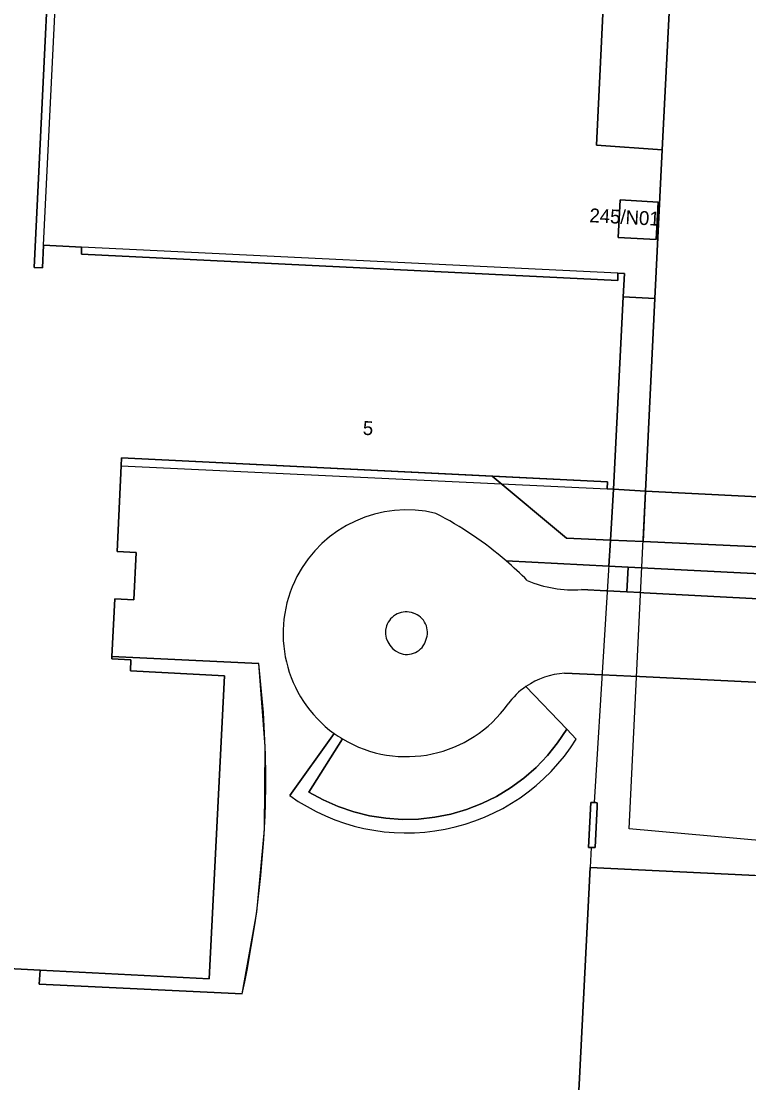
# Model space of a CAD drawing. Extents: x 161758 to 162722, y 384793 to 385405.
# Drawn here: x 162011.7 to 162064.1, y 385249.7 to 385326.1 of the extents above; entities that cross this region are included whole.
import ezdxf

# ---------------------------------------------------------------- set-up
doc = ezdxf.new("R2010")
doc.units = 0
for name, color, linetype in [('IMGEO_Erf', 7, 'Continuous'), ('IMGEO_Groenvoorziening', 7, 'Continuous'), ('IMGEO_Haag', 7, 'Continuous'), ('IMGEO_Muur', 7, 'Continuous'), ('IMGEO_Pand', 7, 'Continuous'), ('IMGEO_Pand_nummerreeks', 7, 'Continuous'), ('IMGEO_Pand_overbouw', 7, 'Continuous'), ('IMGEO_Parkeervlak_open', 7, 'Continuous'), ('IMGEO_Rijbaan_lokaal_gesloten', 7, 'Continuous'), ('IMGEO_Rijbaan_lokaal_open', 7, 'Continuous'), ('IMGEO_Voetpad_open', 7, 'Continuous')]:
    doc.layers.add(name, color=color, linetype=linetype)

msp = doc.modelspace()

# ---------------------------------------------------------------- linework, layer by layer
at = {"layer": 'IMGEO_Erf'}
for points in [[(162000.222, 385344.237), (162014.352, 385343.552), (162012.641, 385308.403), (162013.228, 385308.374), (162013.321, 385310.001), (162015.604, 385309.889), (162016.05, 385309.863), (162016.038, 385309.353), (162054.674, 385307.455), (162054.682, 385307.985), (162055.146, 385307.978), (162055.062, 385306.286), (162057.335, 385306.161), (162057.875, 385316.893), (162053.132, 385317.221), (162054.39, 385343.133)], [(162046.639, 385287.263), (162054.026, 385286.89), (162054.142, 385288.756), (162050.979, 385288.899), (162045.633, 385293.362), (162018.94, 385294.688), (162018.914, 385294.105), (162018.606, 385287.935), (162019.994, 385287.867), (162019.826, 385284.453), (162018.438, 385284.521), (162018.242, 385280.372), (162028.809, 385279.859)], [(162121.521, 385275.665), (162083.133, 385277.615), (162056.237, 385278.926), (162055.602, 385278.957), (162053.548, 385279.049), (162050.835, 385279.171)], [(162048.062, 385278.214), (162050.992, 385275.146), (162051.687, 385274.418)], [(162034.242, 385274.83), (162031.044, 385270.355)], [(162031.044, 385270.355), (162034.242, 385274.83)], [(162051.687, 385274.418), (162050.992, 385275.146), (162050.338, 385274.163), (162049.601, 385273.242), (162048.787, 385272.388), (162047.9, 385271.609), (162046.949, 385270.911), (162045.941, 385270.298), (162044.883, 385269.776), (162043.783, 385269.348), (162042.65, 385269.018), (162041.492, 385268.789), (162040.319, 385268.661), (162039.14, 385268.637), (162037.962, 385268.716), (162036.796, 385268.897), (162035.651, 385269.18), (162034.534, 385269.561), (162033.455, 385270.039), (162032.422, 385270.61), (162034.844, 385274.435)], [(162051.88, 385249.095), (162051.925, 385250), (162052.677, 385265.163), (162064.107, 385264.629)], [(162027.622, 385256.076), (162012.996, 385256.776), (162013.072, 385257.772), (162010.781, 385257.887), (162008.908, 385257.981), (162008.518, 385250.179), (162008.288, 385245.576)]]:
    msp.add_lwpolyline(points, dxfattribs=at)
for points in [[(162057.575, 385313.122), (162057.439, 385310.413), (162054.692, 385310.56), (162054.837, 385313.268)], [(162090.663, 385298.763), (162090.024, 385298.468), (162088.823, 385297.914), (162088.821, 385297.876), (162089.919, 385297.91), (162089.575, 385290.639), (162056.667, 385292.277), (162056.492, 385288.65), (162071.152, 385287.989), (162083.046, 385287.356), (162083.181, 385290.342), (162090.009, 385289.962), (162089.851, 385287.051), (162090.151, 385287.029), (162090.553, 385296.234)], [(162054.37, 385292.426), (162053.916, 385292.449), (162053.942, 385292.95), (162045.633, 385293.362), (162050.979, 385288.899), (162054.142, 385288.756)], [(162053.047, 385266.607), (162052.763, 385266.616), (162052.566, 385266.623), (162052.73, 385269.864), (162053.089, 385269.85), (162053.197, 385269.841), (162053.183, 385269.545)]]:
    msp.add_lwpolyline(points, close=True, dxfattribs=at)
for centre, radius, start, end in [((162039.477, 385282.029), 8.909, 76.4177, 152.61427), ((162029.557, 385267.449), 26.16, 49.23532, 62.66778), ((162039.459, 385282.031), 8.893, 152.57568, 234.07717), ((161959.246, 385271.428), 70.072, 0.30886, 6.91025), ((162051.158, 385273.74), 5.44, 93.39986, 124.68064), ((162039.775, 385282.606), 9.543, 234.56735, 238.89119), ((162039.45, 385282.117), 14.457, 234.44756, 327.82195), ((162039.45, 385282.117), 14.457, 234.44756, 327.82195), ((161982.112, 385271.204), 47.209, 358.25711, 0.73083), ((161954.12, 385272.027), 75.213, 347.75566, 358.27869), ((162065.136, 385283.844), 19.243, 266.93392, 288.19884)]:
    msp.add_arc(centre, radius, start, end, dxfattribs=at)
at = {"layer": 'IMGEO_Groenvoorziening'}
msp.add_lwpolyline([(162098.143, 385284.617), (162074.929, 385285.836), (162055.428, 385286.819), (162055.318, 385285.029), (162056.316, 385284.979), (162056.544, 385284.967), (162096.901, 385282.85)], dxfattribs=at)
for centre, radius, start, end in [((162039.428, 385282.095), 1.493, 69.61819, 161.21417), ((162039.509, 385282.106), 1.456, 337.74961, 72.4619), ((162039.559, 385282.118), 1.612, 163.47846, 247.09975), ((162039.48, 385281.959), 1.435, 247.54518, 343.64003)]:
    msp.add_arc(centre, radius, start, end, dxfattribs=at)
at = {"layer": 'IMGEO_Haag'}
for centre, radius, start, end in [((162039.428, 385282.095), 1.493, 69.61819, 161.21417), ((162039.509, 385282.106), 1.456, 337.74961, 72.4619), ((162039.559, 385282.118), 1.612, 163.47846, 247.09975), ((162039.48, 385281.959), 1.435, 247.54518, 343.64003)]:
    msp.add_arc(centre, radius, start, end, dxfattribs=at)
at = {"layer": 'IMGEO_Muur'}
msp.add_lwpolyline([(162057.875, 385316.893), (162053.132, 385317.221), (162054.39, 385343.133)], dxfattribs=at)
at = {"layer": 'IMGEO_Pand'}
for points in [[(162055.062, 385306.286), (162055.146, 385307.978), (162054.682, 385307.985), (162054.674, 385307.455), (162016.038, 385309.353), (162016.05, 385309.863), (162015.604, 385309.889), (162013.321, 385310.001), (162013.228, 385308.374), (162012.641, 385308.403), (162014.352, 385343.552), (162000.222, 385344.237), (162000, 385339.778), (161998.661, 385312.884), (161998.064, 385312.914), (161996.529, 385312.991), (161983.184, 385313.656), (161983.117, 385317.361)], [(162091.282, 385324.562), (162092.129, 385341.645), (162076.599, 385342.392), (162069.876, 385342.73), (162066.145, 385342.918), (162059.203, 385343.267), (162057.875, 385316.893), (162057.335, 385306.161), (162056.667, 385292.277), (162089.575, 385290.639), (162089.919, 385297.91), (162088.821, 385297.876), (162088.823, 385297.914), (162088.856, 385298.567), (162088.976, 385300.882), (162089.397, 385300.836), (162089.498, 385302.937), (162089.079, 385302.969), (162089.102, 385303.241), (162088.454, 385303.297), (162088.504, 385303.874), (162089.645, 385303.85)], [(162008.288, 385245.576), (162008.518, 385250.179), (162008.908, 385257.981), (162010.781, 385257.887), (162013.072, 385257.772), (162025.247, 385257.16), (162026.337, 385278.987), (162019.578, 385279.344), (162019.609, 385280.14), (162018.234, 385280.198), (162018.242, 385280.372), (162018.438, 385284.521), (162019.826, 385284.453), (162019.994, 385287.867), (162018.606, 385287.935), (162018.914, 385294.105), (162018.94, 385294.688), (162045.633, 385293.362), (162053.942, 385292.95), (162053.916, 385292.449), (162054.37, 385292.426), (162055.062, 385306.286)], [(162064.107, 385264.629), (162052.677, 385265.163), (162051.925, 385250), (162051.88, 385249.095)]]:
    msp.add_lwpolyline(points, dxfattribs=at)
for points in [[(162057.575, 385313.122), (162054.837, 385313.268), (162054.692, 385310.56), (162057.439, 385310.413)], [(162053.183, 385269.545), (162053.197, 385269.841), (162053.089, 385269.85), (162052.73, 385269.864), (162052.566, 385266.623), (162052.763, 385266.616), (162053.047, 385266.607)]]:
    msp.add_lwpolyline(points, close=True, dxfattribs=at)
msp.add_arc((162065.136, 385283.844), 19.243, 266.93392, 288.19884, dxfattribs=at)
at = {"layer": 'IMGEO_Pand_overbouw'}
for points in [[(161998.064, 385312.914), (161998.661, 385312.884), (162000, 385339.778), (162000.222, 385344.237), (162014.352, 385343.552), (162012.641, 385308.403), (162013.228, 385308.374), (162013.321, 385310.001), (162015.024, 385344.711), (162000, 385345.458), (161999.676, 385345.474)], [(162016.05, 385309.863), (162016.038, 385309.353), (162054.674, 385307.455), (162054.682, 385307.985)], [(162057.335, 385306.161), (162055.062, 385306.286), (162054.37, 385292.426), (162056.667, 385292.277)], [(162053.916, 385292.449), (162053.942, 385292.95), (162018.94, 385294.688), (162018.914, 385294.105)], [(162013.072, 385257.772), (162012.996, 385256.776), (162027.622, 385256.076), (162028.679, 385261.962), (162029.231, 385267.917), (162029.274, 385273.897), (162028.809, 385279.859), (162018.242, 385280.372), (162018.234, 385280.198), (162019.609, 385280.14), (162019.578, 385279.344), (162026.337, 385278.987), (162025.247, 385257.16)]]:
    msp.add_lwpolyline(points, close=True, dxfattribs=at)
for points in [[(162056.667, 385292.277), (162054.37, 385292.426), (162052.968, 385269.855), (162053.089, 385269.85), (162053.197, 385269.841), (162053.183, 385269.543), (162053.047, 385266.607), (162052.767, 385266.616), (162052.677, 385265.163), (162064.107, 385264.629)], [(162071.146, 385265.564), (162071.273, 385266.531), (162055.497, 385267.968), (162056.667, 385292.277)]]:
    msp.add_lwpolyline(points, dxfattribs=at)
msp.add_arc((162065.136, 385283.844), 19.243, 266.93392, 288.19884, dxfattribs=at)
at = {"layer": 'IMGEO_Parkeervlak_open'}
for points in [[(162055.428, 385286.819), (162054.026, 385286.89), (162046.639, 385287.263)], [(162052.057, 385285.194), (162053.849, 385285.103), (162053.915, 385285.1), (162055.318, 385285.029), (162055.428, 385286.819)], [(162050.992, 385275.146), (162048.062, 385278.214)], [(162034.844, 385274.435), (162032.422, 385270.61), (162033.455, 385270.039), (162034.534, 385269.561), (162035.651, 385269.18), (162036.796, 385268.897), (162037.962, 385268.716), (162039.14, 385268.637), (162040.319, 385268.661), (162041.492, 385268.789), (162042.65, 385269.018), (162043.783, 385269.348), (162044.883, 385269.776), (162045.941, 385270.298), (162046.949, 385270.911), (162047.9, 385271.609), (162048.787, 385272.388), (162049.601, 385273.242), (162050.338, 385274.163), (162050.992, 385275.146)]]:
    msp.add_lwpolyline(points, dxfattribs=at)
for centre, radius, start, end in [((162029.253, 385267.116), 26.612, 44.74633, 49.20624), ((162051.471, 385293.653), 8.479, 246.96179, 273.96129), ((162051.176, 385273.729), 5.46, 124.77643, 143.78563), ((162039.451, 385282.117), 8.958, 239.05259, 324.808)]:
    msp.add_arc(centre, radius, start, end, dxfattribs=at)
at = {"layer": 'IMGEO_Rijbaan_lokaal_gesloten'}
msp.add_lwpolyline([(162059.203, 385343.267), (162054.749, 385343.46), (162054.407, 385343.475), (162054.39, 385343.133), (162053.132, 385317.221), (162057.875, 385316.893)], close=True, dxfattribs=at)
at = {"layer": 'IMGEO_Rijbaan_lokaal_open'}
for points in [[(162096.901, 385282.85), (162056.544, 385284.967), (162056.316, 385284.979), (162055.318, 385285.029), (162053.915, 385285.1), (162053.849, 385285.103), (162052.057, 385285.194)], [(162050.835, 385279.171), (162053.548, 385279.049), (162055.602, 385278.957), (162056.237, 385278.926), (162083.133, 385277.615), (162121.521, 385275.665), (162121.795, 385281.655), (162108.914, 385282.264)]]:
    msp.add_lwpolyline(points, dxfattribs=at)
for centre, radius, start, end in [((162039.477, 385282.029), 8.909, 76.4177, 152.61427), ((162029.557, 385267.449), 26.16, 49.23532, 62.66778), ((162029.253, 385267.116), 26.612, 44.74633, 49.20624), ((162039.459, 385282.031), 8.893, 152.57568, 234.07717), ((162051.471, 385293.653), 8.479, 246.96179, 273.96129), ((162039.428, 385282.095), 1.493, 69.61819, 161.21417), ((162039.509, 385282.106), 1.456, 337.74961, 72.4619), ((162039.559, 385282.118), 1.612, 163.47846, 247.09975), ((162039.48, 385281.959), 1.435, 247.54518, 343.64003), ((162051.158, 385273.74), 5.44, 93.39986, 124.68064), ((162051.176, 385273.729), 5.46, 124.77643, 143.78563), ((162039.451, 385282.117), 8.958, 239.05259, 324.808), ((162039.775, 385282.606), 9.543, 234.56735, 238.89119)]:
    msp.add_arc(centre, radius, start, end, dxfattribs=at)
at = {"layer": 'IMGEO_Voetpad_open'}
for points in [[(162057.335, 385306.161), (162055.062, 385306.286), (162054.37, 385292.426), (162056.667, 385292.277)], [(162056.667, 385292.277), (162054.37, 385292.426), (162054.142, 385288.756), (162056.492, 385288.65)]]:
    msp.add_lwpolyline(points, close=True, dxfattribs=at)
for points in [[(162088.856, 385298.567), (162088.823, 385297.914), (162090.024, 385298.468), (162090.663, 385298.763), (162090.553, 385296.234), (162090.151, 385287.029), (162089.851, 385287.051), (162090.009, 385289.962), (162083.181, 385290.342), (162083.046, 385287.356), (162071.152, 385287.989), (162056.492, 385288.65), (162054.142, 385288.756), (162054.026, 385286.89), (162055.428, 385286.819), (162074.929, 385285.836), (162098.143, 385284.617), (162098.133, 385286.639), (162092.186, 385286.922), (162092.793, 385299.072), (162093.769, 385299.017), (162093.924, 385298.849), (162098.178, 385298.601)], [(162028.809, 385279.859), (162018.242, 385280.372), (162018.234, 385280.198), (162019.609, 385280.14), (162019.578, 385279.344), (162026.337, 385278.987), (162025.247, 385257.16), (162013.072, 385257.772), (162012.996, 385256.776), (162027.622, 385256.076)]]:
    msp.add_lwpolyline(points, dxfattribs=at)
for centre, radius, start, end in [((161959.246, 385271.428), 70.072, 0.30886, 6.91025), ((161982.112, 385271.204), 47.209, 358.25711, 0.73083), ((161954.12, 385272.027), 75.213, 347.75566, 358.27869)]:
    msp.add_arc(centre, radius, start, end, dxfattribs=at)

# ---------------------------------------------------------------- texts
at = {"layer": 'IMGEO_Pand_nummerreeks'}
for s, rotation, p in [('245/N01', 357.00907, (162052.614, 385311.671)), ('5', 357.15813, (162036.29, 385296.349))]:
    msp.add_text(s, height=1, rotation=rotation, dxfattribs=at).set_placement(p)

doc.saveas('drawing.dxf')
